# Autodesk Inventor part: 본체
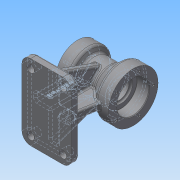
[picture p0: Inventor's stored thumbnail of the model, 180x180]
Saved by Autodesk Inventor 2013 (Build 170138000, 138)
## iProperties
Created: 2015-08
Part Number: 본체
Material: 일반
Document SubType Name: Modeling
Designer: Administrator
Density: 1 g/cm^3
Author: Administrator
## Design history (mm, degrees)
sketch "스케치2"
  geometry: L1 (0, 0)-(90, 0); L2 (0, 0)-(0, 35); L3 (0, 35)-(20, 35); L4 (20, 35)-(25.196, 26); L5 (25.196, 26)-(53.315, 26); L6 (53.315, 26)-(70, 40); L7 (70, 40)-(90, 40); L8 (90, 40)-(90, 0)
  constraints: 16 end point, 3 parallel, 2 perpendicular, 1 horizontal
  dimensions: "d2" = 90 distance of L1.start L1.end; "d3" = 70 diameter of L3 L1; "d5" = 80 diameter of L7 L1; "d6" = 20 distance of L2.end L3.end; "d7" = 60 deg angle of L5 L4; "d8" = 40 deg angle of L5 L6; "d9" = 20 distance of L6.end L7.end; "d11" = 52 diameter of L5 L1
revolve "회전1" sketch "스케치2" stored, may be unused: angle "d12" = 90 deg
sketch "스케치4"
  geometry: L1 (-61, -78)-(61, -78); L2 (61, -78)-(61, -90); L3 (61, -90)-(-61, -90); L4 (-61, -90)-(-61, -78); C1 r 35 at (0, 0) reference; 1 further point
  constraints: 8 end point, 2 parallel, 1 horizontal, 1 midpoint, 1 perpendicular, 1 vertical alignment
  dimensions: "d15" = 12 distance of L1.end L2.end; "d17" = 90 distance from line of L3 C1.centre; "d18" = 122 distance of L2.end L3.end
extrude "돌출1" join sketch "스케치4" distance "d19" = 80; taper "d20" = 0 deg
sketch "스케치5"
  geometry: C1 r 40 at (0, 0) reference; C2 r 26 at (0, 0)
  constraints: 1 centre point, 1 coincident
  dimensions: "d21" = 52 diameter of C2
extrude "돌출2" cut sketch "스케치5" distance "d22" = 20; taper "d23" = 0 deg
sketch "스케치6"
  geometry: C1 r 26 at (0, 0) reference; C2 r 19 at (0, 0)
  constraints: 1 centre point, 1 coincident
  dimensions: "d24" = 38 diameter of C2
extrude "돌출3" cut sketch "스케치6" distance "d25" = 3; taper "d26" = 0 deg
sketch "스케치7"
  geometry: C1 r 35 at (0, 0) reference; C2 r 20 at (0, 0)
  constraints: 1 centre point, 1 coincident
  dimensions: "d27" = 40 diameter of C2
extrude "돌출4" cut sketch "스케치7" distance "d28" = 17; taper "d29" = 0 deg
sketch "스케치8"
  geometry: C1 r 20 at (0, 0) reference; C2 r 16 at (0, 0)
  constraints: 1 centre point, 1 coincident
  dimensions: "d30" = 32 diameter of C2
extrude "돌출5" cut sketch "스케치8" stored distance "d31" = 17; taper "d32" = 0 deg
node "작업 평면1"
sketch "스케치10"
  geometry: L1 (61, -78)-(61, -90) reference; L2 (61, -90)-(-61, -90) reference; L3 (-61, -90)-(-61, -78) reference; L4 (-61, -78)-(61, -78) reference; L5 (61, -78)-(61, -90) reference; L6 (61, -90)-(-61, -90) reference; L7 (-61, -90)-(-61, -78) reference; L8 (-61, -78)-(61, -78) reference; L9 (-25.091, -6.815)-(-51, -78); L10 (25.091, -6.815)-(51, -78); C1 r 16 at (0, 0) reference; C2 r 26 at (0, 0) reference; C3 r 16 at (0, 0) reference; C4 r 35 at (0, 0) reference; A1 r 26 centre (0, 0) between (-25.091, -6.815) and (25.091, -6.815) reference; 1 further point
  constraints: 4 end point, 2 point on circle, 2 point on line, 1 equal length
  dimensions: "d33" = 70 deg angle of L4 L10; "d34" = 10 distance from line of L1 L10.end; "d35" = 70 deg angle of L4 L9
extrude "돌출6" join sketch "스케치10" stored distance "d37" = 12; taper "d38" = 0 deg
sketch "스케치11"
  geometry: L1 (90, 26)-(70, 26) reference; L2 (70, 26)-(70, 19) reference; L3 (70, 19)-(67, 19) reference; L4 (67, 19)-(67, 16) reference; L5 (67, 16)-(17, 16) reference; L6 (17, 16)-(17, 20) reference; L7 (17, 20)-(0, 20) reference; L8 (0, 20)-(0, 35) reference; L9 (0, 35)-(20, 35) reference; L10 (20, 35)-(25.196, 26) reference; L11 (25.196, 26)-(53.315, 26) reference; L12 (53.315, 26)-(70, 40) reference; L13 (70, 40)-(90, 40) reference; L14 (90, 40)-(90, 26) reference; L15 (80, -90)-(0, -90) reference; L16 (0, -90)-(0, -78) reference; L17 (0, -78)-(34, -78) reference; L18 (34, -78)-(34, -26) reference; L19 (34, -26)-(25.196, -26) reference; L20 (25.196, -26)-(20, -35) reference; L21 (20, -35)-(0, -35) reference; L22 (0, -35)-(0, -20) reference; L23 (0, -20)-(17, -20) reference; L24 (17, -20)-(17, -16) reference; L25 (17, -16)-(67, -16) reference; L26 (67, -16)-(67, -19) reference; L27 (67, -19)-(70, -19) reference; L28 (70, -19)-(70, -26) reference; L29 (70, -26)-(90, -26) reference; L30 (90, -26)-(90, -40) reference; L31 (90, -40)-(70, -40) reference; L32 (70, -40)-(53.315, -26) reference; L33 (53.315, -26)-(46, -26) reference; L34 (46, -26)-(46, -78) reference; L35 (46, -78)-(80, -78) reference; L36 (80, -78)-(80, -90) reference; L37 (76.7, -40)-(70, -78); L38 (10, -35)-(10, -78); 1 further point
  constraints: 4 end point, 3 point on line, 1 midpoint, 1 parallel
  dimensions: "d39" = 10 distance of L35.end L37.end; "d40" = 80 deg angle of L35 L37; "d41" = 10 distance between parallel lines of L16 L38
  node "절단 모서리 투영3"
feature "리브1" dims "d42" = 1, "d43" = 12, "d44" = 0, "d45" = 0, "d46" = 1, "d47" = 1
feature "리브2" dims "d48" = 1, "d49" = 12, "d50" = 0, "d51" = 0, "d52" = 1, "d53" = 1
sketch "스케치12"
  geometry: C1 r 26 at (0, 0) reference; 1 further point
  constraints: 1 vertical alignment
  dimensions: "d54" = 33 distance of C1.centre point (0, 33)
hole "구멍1" sketch "스케치12" at (0, 33) diameter "d55" = 3.242; stored, may be unused: countersink angle "d59" = 90 deg, drill point angle "d61" = 118 deg; dims "d56" = 10, "d57" = 4, "d58" = 2, "d60" = 13
sketch "스케치13"
  geometry: C1 r 20 at (0, 0) reference; 1 further point
  constraints: 1 vertical alignment
  dimensions: "d65" = 27 distance of C1.centre point (0, 27)
hole "구멍2" sketch "스케치13" at (0, 27) diameter "d66" = 3.242; stored, may be unused: countersink angle "d70" = 90 deg, drill point angle "d72" = 118 deg; dims "d67" = 10, "d68" = 4, "d69" = 2, "d71" = 13
sketch "스케치14"
  geometry: L1 (-6, -78)-(-51, -78) reference; L2 (-30, -54)-(-30, -60); L3 (-18, -54)-(-18, -60); L4 (6, -78)-(51, -78) reference; L5 (51, -78)-(61, -78) reference; L6 (61, -78)-(61, -90) reference; L7 (61, -90)-(-61, -90) reference; L8 (-61, -90)-(-61, -78) reference; L9 (-61, -78)-(-51, -78) reference; L10 (-51, -78)-(-25.091, -6.815) reference; L11 (25.091, -6.815)-(51, -78) reference; L12 (6, -25.298)-(6, -78) reference; L13 (-51, -78)-(-6, -78) reference; L14 (-6, -78)-(-6, -25.298) reference; C1 r 16 at (0, 0) reference; A1 r 26 centre (0, 0) between (-25.091, -6.815) and (-6, -25.298) reference; A2 r 6 centre (-24, -54) between (-18, -54) and (-30, -54); A3 r 6 centre (-24, -60) between (-30, -60) and (-18, -60); A4 r 26 centre (0, 0) between (25.091, -6.815) and (-25.091, -6.815) reference; A5 r 26 centre (0, 0) between (6, -25.298) and (25.091, -6.815) reference; A6 r 26 centre (0, 0) between (-25.091, -6.815) and (-6, -25.298) reference
  constraints: 4 end point, 4 point on circle, 2 centre point, 2 tangent, 1 parallel, 1 vertical alignment
  dimensions: "d76" = 12 diameter of A2; "d77" = 12 diameter of A3; "d78" = 18 dimension on A3 A2; "d79" = 24 horizontal distance of A1.centre A3.centre; "d80" = 18 distance from line of L1 A3.centre; "d81" = 6 distance of L2.end L2.start
extrude "돌출7" cut sketch "스케치14" stored distance "d82" = 12; taper "d83" = 0 deg
sketch "스케치15"
  geometry: L1 (0, 0)-(0, 43.518) reference; L2 (-10, -12)-(70, -12) reference; L3 (-10, 0)-(70, 0) reference; 2 further points
  constraints: 1 other
  dimensions: "d84" = 16 distance from line of point (16, 24) L1; "d86" = 24 distance from line of L3 point (16, 24)
feature "엠보싱1" sketch "스케치15" dims "d2" = 90, "d3" = 70, "d5" = 80, "d6" = 20, "d7" = 60 deg, "d8" = 40 deg, "d9" = 20, "d11" = 52, "d87" = 0.5, "d88" = 0
chamfer "모따기1" distance "d89" = 1; stored, may be unused: second distance "d90" = 2, angle "d91" = 45 deg
fillet "모깎기1" dims "d92" = 3
fillet "모깎기2" dims "d93" = 0.3
fillet "모깎기3" dims "d94" = 5
fillet "모깎기4" dims "d95" = 14
sketch "스케치16"
  geometry: L1 (14, -14)-(66, -14) reference; L2 (80, 94)-(80, 0) reference; L3 (46, 53)-(70, 53) reference; L4 (14, 0)-(66, 0); L5 (66, 94)-(66, 0); C1 r 6 at (66, 0); C2 r 6 at (66, 94); C3 r 6 at (14, 94); C4 r 6 at (14, 0); 5 further points
  constraints: 4 centre point, 4 end point, 4 midpoint, 3 horizontal alignment, 3 vertical alignment, 1 parallel, 1 perpendicular
  dimensions: "d96" = 12 diameter of C1; "d97" = 12 diameter of C2; "d98" = 12 diameter of C3; "d99" = 12 diameter of C4; "d100" = 52 distance of L4.end L4.start; "d101" = 94 distance of L4.end L5.start
extrude "돌출8" cut sketch "스케치16" stored distance "d102" = 12; taper "d103" = 0 deg
fillet "모깎기5" dims "d104" = 3
fillet "모깎기6" dims "d105" = 3
fillet "모깎기7" dims "d106" = 3
fillet "모깎기8" dims "d107" = 3
node "솔리드1"
pattern_circular "원형 패턴1" dims angle "d63" = 360 deg
pattern_circular "원형 패턴2" dims angle "d74" = 360 deg
mirror "대칭1"
node "절단 모서리 투영1"
node "절단 모서리 투영2"
node "절단 모서리 투영4"
